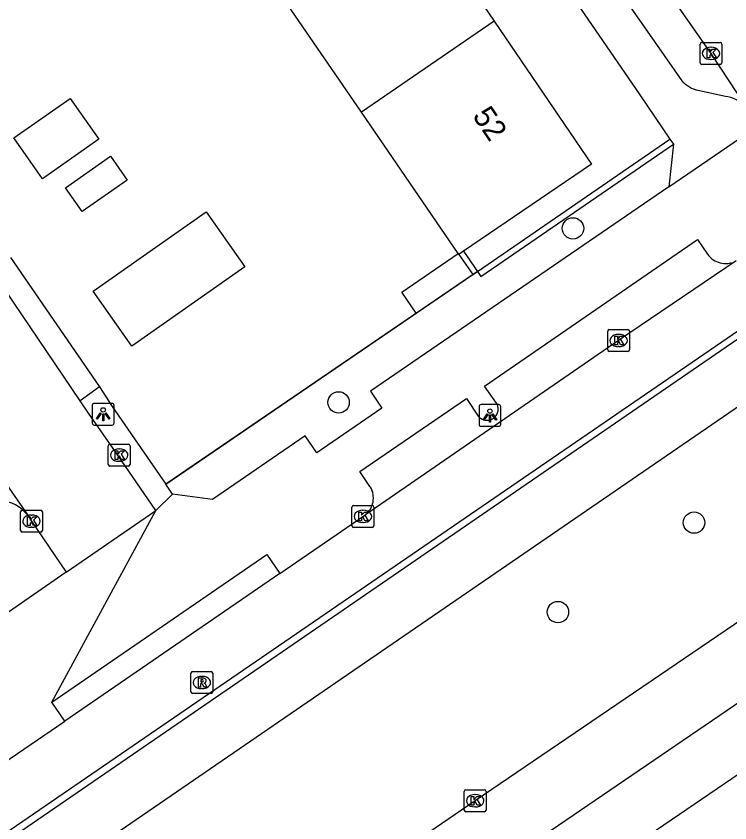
# Model space of a CAD drawing. Extents: x 157466 to 158888, y 383063 to 384677.
# Drawn here: x 158451.79 to 158484.41, y 383570.32 to 383607.2 of the extents above; entities that cross this region are included whole.
import ezdxf

# ---------------------------------------------------------------- set-up
doc = ezdxf.new("R2010")
doc.units = 0
for name, color, linetype in [('IMGEO_Boom', 7, 'Continuous'), ('IMGEO_Fietspad_gesloten', 7, 'Continuous'), ('IMGEO_Groenvoorziening', 7, 'Continuous'), ('IMGEO_Haag', 7, 'Continuous'), ('IMGEO_Hek', 7, 'Continuous'), ('IMGEO_Kolk', 7, 'Continuous'), ('IMGEO_Lichtpunt', 7, 'Continuous'), ('IMGEO_Pand', 7, 'Continuous'), ('IMGEO_Pand_nummerreeks', 7, 'Continuous'), ('IMGEO_Rijbaan_lokaal_open', 7, 'Continuous'), ('IMGEO_Rijbaan_regionaal_gesloten', 7, 'Continuous'), ('IMGEO_Rioolput', 7, 'Continuous'), ('IMGEO_Voetpad_open', 7, 'Continuous')]:
    doc.layers.add(name, color=color, linetype=linetype)

msp = doc.modelspace()

# ---------------------------------------------------------------- linework, layer by layer
at = {"layer": 'IMGEO_Boom'}
for centre in [(158477.239, 383597.497), (158466.526, 383589.538), (158482.772, 383584.047), (158476.55, 383579.952)]:
    msp.add_circle(centre, 0.489, dxfattribs=at)
at = {"layer": 'IMGEO_Fietspad_gesloten'}
for points in [[(158619.533, 383684.885), (158594.652, 383667.82), (158523.57, 383619.052), (158500, 383602.881), (158449.207, 383568.025), (158400.089, 383534.274)], [(158382.666, 383518.924), (158382.786, 383519.037), (158385.186, 383520.921), (158400.504, 383531.525), (158500, 383599.794), (158509.882, 383606.575), (158524.995, 383616.939), (158597.382, 383666.576), (158618.032, 383680.773)]]:
    msp.add_lwpolyline(points, dxfattribs=at)
at = {"layer": 'IMGEO_Groenvoorziening'}
for points in [[(158472.655, 383595.381), (158472.869, 383595.532)], [(158458.626, 383585.798), (158470.072, 383593.62)]]:
    msp.add_lwpolyline(points, dxfattribs=at)
at = {"layer": 'IMGEO_Haag'}
for points in [[(158472.869, 383595.532), (158481.671, 383601.572)], [(158472.869, 383595.532), (158473.027, 383595.3), (158481.829, 383601.34)]]:
    msp.add_lwpolyline(points, dxfattribs=at)
at = {"layer": 'IMGEO_Hek'}
for points in [[(158472.238, 383596.448), (158472.869, 383595.532)], [(158472.869, 383595.532), (158458.626, 383585.798)]]:
    msp.add_lwpolyline(points, dxfattribs=at)
at = {"layer": 'IMGEO_Kolk'}
for p, q in [((158483.047, 383605.07), (158483.047, 383605.922)), ((158483.122, 383605.996), (158483.974, 383605.996)), ((158483.535, 383605.776), (158483.56, 383605.776)), ((158484.048, 383605.922), (158484.048, 383605.07)), ((158483.974, 383604.996), (158483.122, 383604.996)), ((158483.558, 383605.216), (158483.533, 383605.216)), ((158478.826, 383591.944), (158478.826, 383592.796)), ((158478.901, 383592.87), (158479.753, 383592.87)), ((158479.827, 383592.796), (158479.827, 383591.944)), ((158479.314, 383592.65), (158479.339, 383592.65)), ((158479.337, 383592.09), (158479.312, 383592.09)), ((158479.753, 383591.87), (158478.901, 383591.87)), ((158456.072, 383587.631), (158456.924, 383587.631)), ((158455.997, 383586.705), (158455.997, 383587.557)), ((158456.485, 383587.411), (158456.51, 383587.411)), ((158456.998, 383587.557), (158456.998, 383586.705)), ((158456.924, 383586.631), (158456.072, 383586.631)), ((158456.508, 383586.851), (158456.483, 383586.851)), ((158467.137, 383583.903), (158467.137, 383584.755)), ((158467.212, 383584.829), (158468.064, 383584.829)), ((158468.138, 383584.755), (158468.138, 383583.903)), ((158451.989, 383583.685), (158451.989, 383584.537)), ((158452.064, 383584.611), (158452.916, 383584.611)), ((158452.477, 383584.391), (158452.502, 383584.391)), ((158452.99, 383584.537), (158452.99, 383583.685)), ((158467.625, 383584.609), (158467.65, 383584.609)), ((158467.648, 383584.049), (158467.623, 383584.049)), ((158452.916, 383583.611), (158452.064, 383583.611)), ((158452.5, 383583.831), (158452.475, 383583.831)), ((158468.064, 383583.829), (158467.212, 383583.829)), ((158472.268, 383570.903), (158472.268, 383571.755)), ((158472.343, 383571.829), (158473.195, 383571.829)), ((158473.269, 383571.755), (158473.269, 383570.903)), ((158472.756, 383571.609), (158472.781, 383571.609)), ((158472.779, 383571.049), (158472.754, 383571.049)), ((158473.195, 383570.829), (158472.343, 383570.829))]:
    msp.add_line(p, q, dxfattribs=at)
for points in [[(158483.047, 383605.07), (158483.047, 383605.922)], [(158483.122, 383605.996), (158483.974, 383605.996)], [(158483.368, 383605.696), (158483.491, 383605.696), (158483.491, 383605.545), (158483.621, 383605.696), (158483.785, 383605.696), (158483.639, 383605.545), (158483.792, 383605.296), (158483.64, 383605.296), (158483.555, 383605.46), (158483.491, 383605.393), (158483.491, 383605.296), (158483.368, 383605.296), (158483.368, 383605.696)], [(158484.048, 383605.922), (158484.048, 383605.07)], [(158483.974, 383604.996), (158483.122, 383604.996)], [(158478.826, 383591.944), (158478.826, 383592.796)], [(158478.901, 383592.87), (158479.753, 383592.87)], [(158479.827, 383592.796), (158479.827, 383591.944)], [(158479.147, 383592.57), (158479.27, 383592.57), (158479.27, 383592.419), (158479.4, 383592.57), (158479.564, 383592.57), (158479.418, 383592.419), (158479.571, 383592.17), (158479.419, 383592.17), (158479.334, 383592.334), (158479.27, 383592.267), (158479.27, 383592.17), (158479.147, 383592.17), (158479.147, 383592.57)], [(158479.753, 383591.87), (158478.901, 383591.87)], [(158456.072, 383587.631), (158456.924, 383587.631)], [(158455.997, 383586.705), (158455.997, 383587.557)], [(158456.318, 383587.331), (158456.441, 383587.331), (158456.441, 383587.18), (158456.571, 383587.331), (158456.735, 383587.331), (158456.589, 383587.18), (158456.742, 383586.931), (158456.59, 383586.931), (158456.505, 383587.095), (158456.441, 383587.028), (158456.441, 383586.931), (158456.318, 383586.931), (158456.318, 383587.331)], [(158456.998, 383587.557), (158456.998, 383586.705)], [(158456.924, 383586.631), (158456.072, 383586.631)], [(158467.137, 383583.903), (158467.137, 383584.755)], [(158467.212, 383584.829), (158468.064, 383584.829)], [(158468.138, 383584.755), (158468.138, 383583.903)], [(158451.989, 383583.685), (158451.989, 383584.537)], [(158452.064, 383584.611), (158452.916, 383584.611)], [(158452.31, 383584.311), (158452.433, 383584.311), (158452.433, 383584.16), (158452.563, 383584.311), (158452.727, 383584.311), (158452.581, 383584.16), (158452.734, 383583.911), (158452.582, 383583.911), (158452.497, 383584.075), (158452.433, 383584.008), (158452.433, 383583.911), (158452.31, 383583.911), (158452.31, 383584.311)], [(158452.99, 383584.537), (158452.99, 383583.685)], [(158467.458, 383584.529), (158467.581, 383584.529), (158467.581, 383584.378), (158467.711, 383584.529), (158467.875, 383584.529), (158467.729, 383584.378), (158467.882, 383584.129), (158467.73, 383584.129), (158467.645, 383584.293), (158467.581, 383584.226), (158467.581, 383584.129), (158467.458, 383584.129), (158467.458, 383584.529)], [(158452.916, 383583.611), (158452.064, 383583.611)], [(158468.064, 383583.829), (158467.212, 383583.829)], [(158472.268, 383570.903), (158472.268, 383571.755)], [(158472.343, 383571.829), (158473.195, 383571.829)], [(158473.269, 383571.755), (158473.269, 383570.903)], [(158472.589, 383571.529), (158472.712, 383571.529), (158472.712, 383571.378), (158472.842, 383571.529), (158473.006, 383571.529), (158472.86, 383571.378), (158473.013, 383571.129), (158472.861, 383571.129), (158472.776, 383571.293), (158472.712, 383571.226), (158472.712, 383571.129), (158472.589, 383571.129), (158472.589, 383571.529)], [(158473.195, 383570.829), (158472.343, 383570.829)]]:
    msp.add_lwpolyline(points, dxfattribs=at)
for centre, start, end in [((158483.124, 383605.92), 91.552, 178.448), ((158483.124, 383605.92), 91.552, 178.448), ((158483.972, 383605.92), 1.552, 88.448), ((158483.972, 383605.92), 1.552, 88.448), ((158483.124, 383605.072), 181.552, 268.448), ((158483.124, 383605.072), 181.552, 268.448), ((158483.972, 383605.072), 271.552, 358.448), ((158483.972, 383605.072), 271.552, 358.448), ((158478.903, 383592.794), 91.552, 178.448), ((158478.903, 383592.794), 91.552, 178.448), ((158479.751, 383592.794), 1.552, 88.448), ((158479.751, 383592.794), 1.552, 88.448), ((158478.903, 383591.946), 181.552, 268.448), ((158478.903, 383591.946), 181.552, 268.448), ((158479.751, 383591.946), 271.552, 358.448), ((158479.751, 383591.946), 271.552, 358.448), ((158456.074, 383587.555), 91.552, 178.448), ((158456.074, 383587.555), 91.552, 178.448), ((158456.922, 383587.555), 1.552, 88.448), ((158456.922, 383587.555), 1.552, 88.448), ((158456.074, 383586.707), 181.552, 268.448), ((158456.074, 383586.707), 181.552, 268.448), ((158456.922, 383586.707), 271.552, 358.448), ((158456.922, 383586.707), 271.552, 358.448), ((158467.214, 383584.753), 91.552, 178.448), ((158467.214, 383584.753), 91.552, 178.448), ((158468.062, 383584.753), 1.552, 88.448), ((158468.062, 383584.753), 1.552, 88.448), ((158452.066, 383584.535), 91.552, 178.448), ((158452.066, 383584.535), 91.552, 178.448), ((158452.914, 383584.535), 1.552, 88.448), ((158452.914, 383584.535), 1.552, 88.448), ((158452.066, 383583.687), 181.552, 268.448), ((158452.066, 383583.687), 181.552, 268.448), ((158452.914, 383583.687), 271.552, 358.448), ((158452.914, 383583.687), 271.552, 358.448), ((158467.214, 383583.905), 181.552, 268.448), ((158467.214, 383583.905), 181.552, 268.448), ((158468.062, 383583.905), 271.552, 358.448), ((158468.062, 383583.905), 271.552, 358.448), ((158472.345, 383571.753), 91.552, 178.448), ((158472.345, 383571.753), 91.552, 178.448), ((158473.193, 383571.753), 1.552, 88.448), ((158473.193, 383571.753), 1.552, 88.448), ((158472.345, 383570.905), 181.552, 268.448), ((158472.345, 383570.905), 181.552, 268.448), ((158473.193, 383570.905), 271.552, 358.448), ((158473.193, 383570.905), 271.552, 358.448)]:
    msp.add_arc(centre, 0.0765, start, end, dxfattribs=at)
for centre, major_axis, ratio, start_param, end_param in [((158483.534, 383605.496), (-0.387, 0.002), 0.722429, 4.712389, 7.853982), ((158483.559, 383605.496), (-0.39, 0.002), 0.717154, 1.570796, 4.712389), ((158479.313, 383592.37), (-0.387, 0.002), 0.722429, 4.712389, 7.853982), ((158479.338, 383592.37), (-0.39, 0.002), 0.717154, 1.570796, 4.712389), ((158456.484, 383587.131), (-0.387, 0.002), 0.722429, 4.712389, 7.853982), ((158456.509, 383587.131), (-0.39, 0.002), 0.717154, 1.570796, 4.712389), ((158452.476, 383584.111), (-0.387, 0.002), 0.722429, 4.712389, 7.853982), ((158452.501, 383584.111), (-0.39, 0.002), 0.717154, 1.570796, 4.712389), ((158467.624, 383584.329), (-0.387, 0.002), 0.722429, 4.712389, 7.853982), ((158467.649, 383584.329), (-0.39, 0.002), 0.717154, 1.570796, 4.712389), ((158472.755, 383571.329), (-0.387, 0.002), 0.722429, 4.712389, 7.853982), ((158472.78, 383571.329), (-0.39, 0.002), 0.717154, 1.570796, 4.712389)]:
    msp.add_ellipse(centre, major_axis=major_axis, ratio=ratio, start_param=start_param, end_param=end_param, dxfattribs=at)
at = {"layer": 'IMGEO_Lichtpunt'}
for p, q in [((158456.169, 383589.497), (158455.361, 383589.497)), ((158456.169, 383589.497), (158455.361, 383589.497)), ((158455.267, 383589.402), (158455.267, 383588.595)), ((158455.267, 383589.402), (158455.267, 383588.595)), ((158456.263, 383588.595), (158456.263, 383589.402)), ((158456.263, 383588.595), (158456.263, 383589.402)), ((158472.945, 383589.349), (158472.945, 383588.542)), ((158472.945, 383589.349), (158472.945, 383588.542)), ((158473.847, 383589.444), (158473.039, 383589.444)), ((158473.847, 383589.444), (158473.039, 383589.444)), ((158473.941, 383588.542), (158473.941, 383589.349)), ((158473.941, 383588.542), (158473.941, 383589.349)), ((158455.361, 383588.501), (158456.169, 383588.501)), ((158455.361, 383588.501), (158456.169, 383588.501)), ((158473.039, 383588.448), (158473.847, 383588.448)), ((158473.039, 383588.448), (158473.847, 383588.448))]:
    msp.add_line(p, q, dxfattribs=at)
for points in [[(158455.641, 383589.066), (158455.68, 383589.038), (158455.492, 383588.776), (158455.454, 383588.803), (158455.641, 383589.066)], [(158455.743, 383589.018), (158455.79, 383589.018), (158455.79, 383588.696), (158455.743, 383588.696), (158455.743, 383589.018)], [(158455.853, 383589.038), (158455.891, 383589.065), (158456.078, 383588.803), (158456.039, 383588.775), (158455.853, 383589.038)], [(158473.319, 383589.013), (158473.358, 383588.985), (158473.17, 383588.723), (158473.132, 383588.75), (158473.319, 383589.013)], [(158473.421, 383588.965), (158473.468, 383588.965), (158473.468, 383588.643), (158473.421, 383588.643), (158473.421, 383588.965)], [(158473.531, 383588.985), (158473.569, 383589.012), (158473.756, 383588.75), (158473.717, 383588.722), (158473.531, 383588.985)]]:
    msp.add_lwpolyline(points, dxfattribs=at)
for centre in [(158455.766, 383589.2), (158473.444, 383589.147)]:
    msp.add_circle(centre, 0.0994, dxfattribs=at)
for centre, start, end in [((158455.361, 383589.402), 90, 180), ((158455.361, 383589.402), 90, 180), ((158456.169, 383589.402), 0, 90), ((158456.169, 383589.402), 0, 90), ((158473.039, 383589.349), 90, 180), ((158473.039, 383589.349), 90, 180), ((158473.847, 383589.349), 0, 90), ((158473.847, 383589.349), 0, 90), ((158455.361, 383588.595), 180, 270), ((158455.361, 383588.595), 180, 270), ((158456.169, 383588.595), 270, 0), ((158456.169, 383588.595), 270, 360), ((158473.039, 383588.542), 180, 270), ((158473.039, 383588.542), 180, 270), ((158473.847, 383588.542), 270, 0), ((158473.847, 383588.542), 270, 360)]:
    msp.add_arc(centre, 0.0946, start, end, dxfattribs=at)
at = {"layer": 'IMGEO_Pand'}
for points in [[(158468.948, 383613.877), (158473.641, 383606.97)], [(158467.571, 383602.813), (158462.856, 383609.705)], [(158473.641, 383606.97), (158467.571, 383602.813)], [(158473.641, 383606.97), (158478.083, 383600.432), (158472.238, 383596.448), (158472.025, 383596.303)], [(158454.255, 383603.441), (158455.565, 383601.579), (158452.991, 383599.769), (158451.681, 383601.632), (158454.255, 383603.441)], [(158471.995, 383596.347), (158467.571, 383602.813)], [(158456.096, 383600.795), (158456.86, 383599.708), (158454.803, 383598.262), (158454.039, 383599.349), (158456.096, 383600.795)], [(158460.47, 383598.248), (158462.234, 383595.736), (158457.079, 383592.114), (158455.315, 383594.624), (158460.47, 383598.248)], [(158470.072, 383593.62), (158469.411, 383594.585), (158471.995, 383596.347)], [(158471.995, 383596.347), (158472.025, 383596.303)], [(158472.025, 383596.303), (158472.655, 383595.381)], [(158470.072, 383593.62), (158472.655, 383595.381)]]:
    msp.add_lwpolyline(points, dxfattribs=at)
at = {"layer": 'IMGEO_Rijbaan_lokaal_open'}
for points in [[(158619.216, 383685.422), (158617.63, 383684.079), (158616.756, 383683.403), (158594.495, 383668.112), (158523.401, 383619.303), (158507.088, 383608.103), (158500, 383603.242), (158404.665, 383537.859)], [(158396.544, 383665.307), (158414.772, 383638.784), (158440.961, 383600.776), (158448.901, 383589.304), (158452.346, 383584.337)], [(158465.095, 383632.213), (158474, 383619.196), (158482.506, 383606.965), (158483.545, 383605.497), (158485.16, 383603.044)], [(158454.709, 383589.606), (158450.508, 383595.811)], [(158484.692, 383596.02), (158479.327, 383592.369), (158467.749, 383584.404)], [(158458.174, 383584.6), (158456.434, 383587.131), (158455.092, 383589.049), (158454.709, 383589.606)], [(158452.346, 383584.337), (158452.491, 383584.112), (158454.081, 383581.774)], [(158454.081, 383581.774), (158458.174, 383584.6)], [(158463.841, 383581.72), (158467.432, 383584.18), (158467.639, 383584.328), (158467.749, 383584.404)], [(158463.841, 383581.72), (158454.013, 383574.964)], [(158447.704, 383570.644), (158451.224, 383573.063), (158454.013, 383574.964)]]:
    msp.add_lwpolyline(points, dxfattribs=at)
at = {"layer": 'IMGEO_Rijbaan_regionaal_gesloten'}
for points in [[(158357.947, 383492.263), (158362.176, 383495.3), (158374.335, 383503.923), (158377.704, 383506.331), (158381.801, 383508.832), (158392.975, 383513.826), (158396.6, 383515.895), (158419.62, 383531.385), (158675.249, 383705.727)], [(158421.008, 383529.093), (158421.837, 383529.639), (158500, 383582.902), (158532.907, 383605.325), (158542.718, 383612.011), (158649.601, 383684.834)], [(158488.049, 383581.718), (158472.766, 383571.328), (158457.465, 383560.876), (158442.175, 383550.47), (158411.628, 383529.655), (158406.471, 383526.137), (158401.509, 383522.775), (158398.999, 383521.064), (158396.311, 383519.274), (158392.334, 383516.949), (158386.367, 383514.043), (158386.117, 383513.939)]]:
    msp.add_lwpolyline(points, dxfattribs=at)
at = {"layer": 'IMGEO_Rioolput'}
for p, q in [((158459.776, 383576.308), (158459.776, 383577.16)), ((158459.851, 383577.234), (158460.703, 383577.234)), ((158460.264, 383577.014), (158460.289, 383577.014)), ((158460.777, 383577.16), (158460.777, 383576.308)), ((158460.703, 383576.234), (158459.851, 383576.234)), ((158460.287, 383576.454), (158460.262, 383576.454))]:
    msp.add_line(p, q, dxfattribs=at)
for points in [[(158459.776, 383576.308), (158459.776, 383577.16)], [(158459.851, 383577.234), (158460.703, 383577.234)], [(158460.365, 383576.932), (158460.113, 383576.934), (158460.113, 383576.534)], [(158460.777, 383577.16), (158460.777, 383576.308)], [(158460.113, 383576.534), (158460.237, 383576.534), (158460.237, 383576.696), (158460.248, 383576.696)], [(158460.291, 383576.853), (158460.237, 383576.853), (158460.237, 383576.772)], [(158460.237, 383576.772), (158460.289, 383576.772)], [(158460.295, 383576.667), (158460.366, 383576.534), (158460.506, 383576.534), (158460.441, 383576.66)], [(158460.703, 383576.234), (158459.851, 383576.234)]]:
    msp.add_lwpolyline(points, dxfattribs=at)
for centre, radius, start, end in [((158459.853, 383577.158), 0.0765, 91.552, 178.448), ((158459.853, 383577.158), 0.0765, 91.552, 178.448), ((158460.364, 383576.822), 0.109, 350.3612, 89.416), ((158460.701, 383577.158), 0.0765, 1.552, 88.448), ((158460.701, 383577.158), 0.0765, 1.552, 88.448), ((158460.247, 383576.643), 0.0533, 26.0293, 88.6989), ((158460.273, 383576.961), 0.19, 274.7715, 282.9687), ((158460.297, 383576.757), 0.0964, 77.0061, 93.1865), ((158460.311, 383576.814), 0.0378, 276.6634, 79.6772), ((158460.362, 383576.822), 0.112, 277.5842, 350.9817), ((158460.346, 383576.607), 0.108, 29.5134, 73.7905), ((158459.853, 383576.31), 0.0765, 181.552, 268.448), ((158459.853, 383576.31), 0.0765, 181.552, 268.448), ((158460.701, 383576.31), 0.0765, 271.552, 358.448), ((158460.701, 383576.31), 0.0765, 271.552, 358.448)]:
    msp.add_arc(centre, radius, start, end, dxfattribs=at)
for centre, major_axis, ratio, start_param, end_param in [((158460.263, 383576.734), (-0.387, 0.002), 0.722429, 4.712389, 7.853982), ((158460.288, 383576.734), (-0.39, 0.002), 0.717154, 1.570796, 4.712389)]:
    msp.add_ellipse(centre, major_axis=major_axis, ratio=ratio, start_param=start_param, end_param=end_param, dxfattribs=at)
at = {"layer": 'IMGEO_Voetpad_open'}
for points in [[(158457.32, 383637.049), (158480.295, 383603.601), (158481.671, 383601.572)], [(158485.16, 383603.044), (158485.059, 383603.142), (158484.951, 383603.231), (158484.834, 383603.31), (158484.711, 383603.378), (158484.583, 383603.435), (158484.45, 383603.48), (158484.313, 383603.513), (158484.205, 383603.53), (158482.88, 383603.815), (158482.863, 383603.82), (158482.759, 383603.854), (158482.658, 383603.898), (158482.562, 383603.951), (158482.471, 383604.012), (158482.386, 383604.081), (158482.307, 383604.158), (158482.235, 383604.241), (158481.423, 383605.393), (158479.87, 383607.632)], [(158481.627, 383599.395), (158485.469, 383602.026)], [(158481.829, 383601.34), (158481.627, 383599.395)], [(158481.671, 383601.572), (158481.829, 383601.34)], [(158481.627, 383599.395), (158467.987, 383590.054), (158468.51, 383589.275), (158465.536, 383587.241), (158464.996, 383588.007), (158460.763, 383585.108), (158458.94, 383585.342)], [(158467.749, 383584.404), (158467.815, 383584.461), (158467.875, 383584.524), (158467.929, 383584.592), (158467.978, 383584.664), (158468.019, 383584.74), (158468.054, 383584.82), (158468.081, 383584.903), (158468.101, 383584.987), (158468.113, 383585.074), (158468.117, 383585.16), (158468.114, 383585.247), (158468.103, 383585.334), (158468.084, 383585.419), (158468.058, 383585.501), (158468.024, 383585.582), (158467.983, 383585.659), (158467.957, 383585.701), (158467.504, 383586.376), (158472.374, 383589.721), (158472.907, 383588.919), (158472.937, 383588.884), (158472.969, 383588.852), (158473.005, 383588.824), (158473.042, 383588.798), (158473.082, 383588.776), (158473.124, 383588.757), (158473.167, 383588.743), (158473.212, 383588.732), (158473.257, 383588.725), (158473.302, 383588.723), (158473.348, 383588.724), (158473.393, 383588.729), (158473.438, 383588.739), (158473.482, 383588.752), (158473.524, 383588.77), (158473.564, 383588.791), (158473.603, 383588.815), (158473.639, 383588.843), (158473.672, 383588.874), (158473.703, 383588.908), (158473.73, 383588.944), (158473.755, 383588.983), (158473.775, 383589.024), (158473.792, 383589.066), (158473.805, 383589.11), (158473.814, 383589.155), (158473.819, 383589.2), (158473.82, 383589.246), (158473.817, 383589.291), (158473.809, 383589.336), (158473.798, 383589.381), (158473.783, 383589.424), (158473.764, 383589.465), (158473.74, 383589.507), (158473.193, 383590.289), (158482.926, 383596.995), (158483.393, 383596.313), (158483.447, 383596.243), (158483.506, 383596.178), (158483.571, 383596.119), (158483.641, 383596.065), (158483.716, 383596.018), (158483.795, 383595.978), (158483.876, 383595.945), (158483.961, 383595.92), (158484.047, 383595.902), (158484.135, 383595.892), (158484.223, 383595.89), (158484.311, 383595.896), (158484.398, 383595.91), (158484.484, 383595.931)], [(158451.528, 383596.17), (158455.6, 383590.247)], [(158455.6, 383590.247), (158454.709, 383589.606)], [(158455.6, 383590.247), (158456.182, 383589.35), (158458.626, 383585.798)], [(158458.94, 383585.342), (158458.626, 383585.798)], [(158458.174, 383584.6), (158458.94, 383585.342)], [(158453.413, 383575.838), (158458.174, 383584.6)], [(158453.413, 383575.838), (158463.241, 383582.594), (158463.841, 383581.72)], [(158454.081, 383581.774), (158449.931, 383578.909)], [(158454.013, 383574.964), (158453.413, 383575.838)]]:
    msp.add_lwpolyline(points, dxfattribs=at)
msp.add_arc((158450.933, 383583.333), 1.733, 35.3831, 87.516, dxfattribs=at)

# ---------------------------------------------------------------- texts
at = {"layer": 'IMGEO_Pand_nummerreeks'}
msp.add_text('52', height=1, rotation=304.1939, dxfattribs=at).set_placement((158472.62, 383602.635))

doc.saveas('drawing.dxf')
